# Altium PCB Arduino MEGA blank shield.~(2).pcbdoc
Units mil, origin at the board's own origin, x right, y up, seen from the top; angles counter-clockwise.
Board outline 4000 x 2100 mil, 2 copper layers (Top Layer, Bottom Layer); 8 components, 79 nets, 94 pads, 0 vias.
Unrouted connection lines stored in the file: 9.
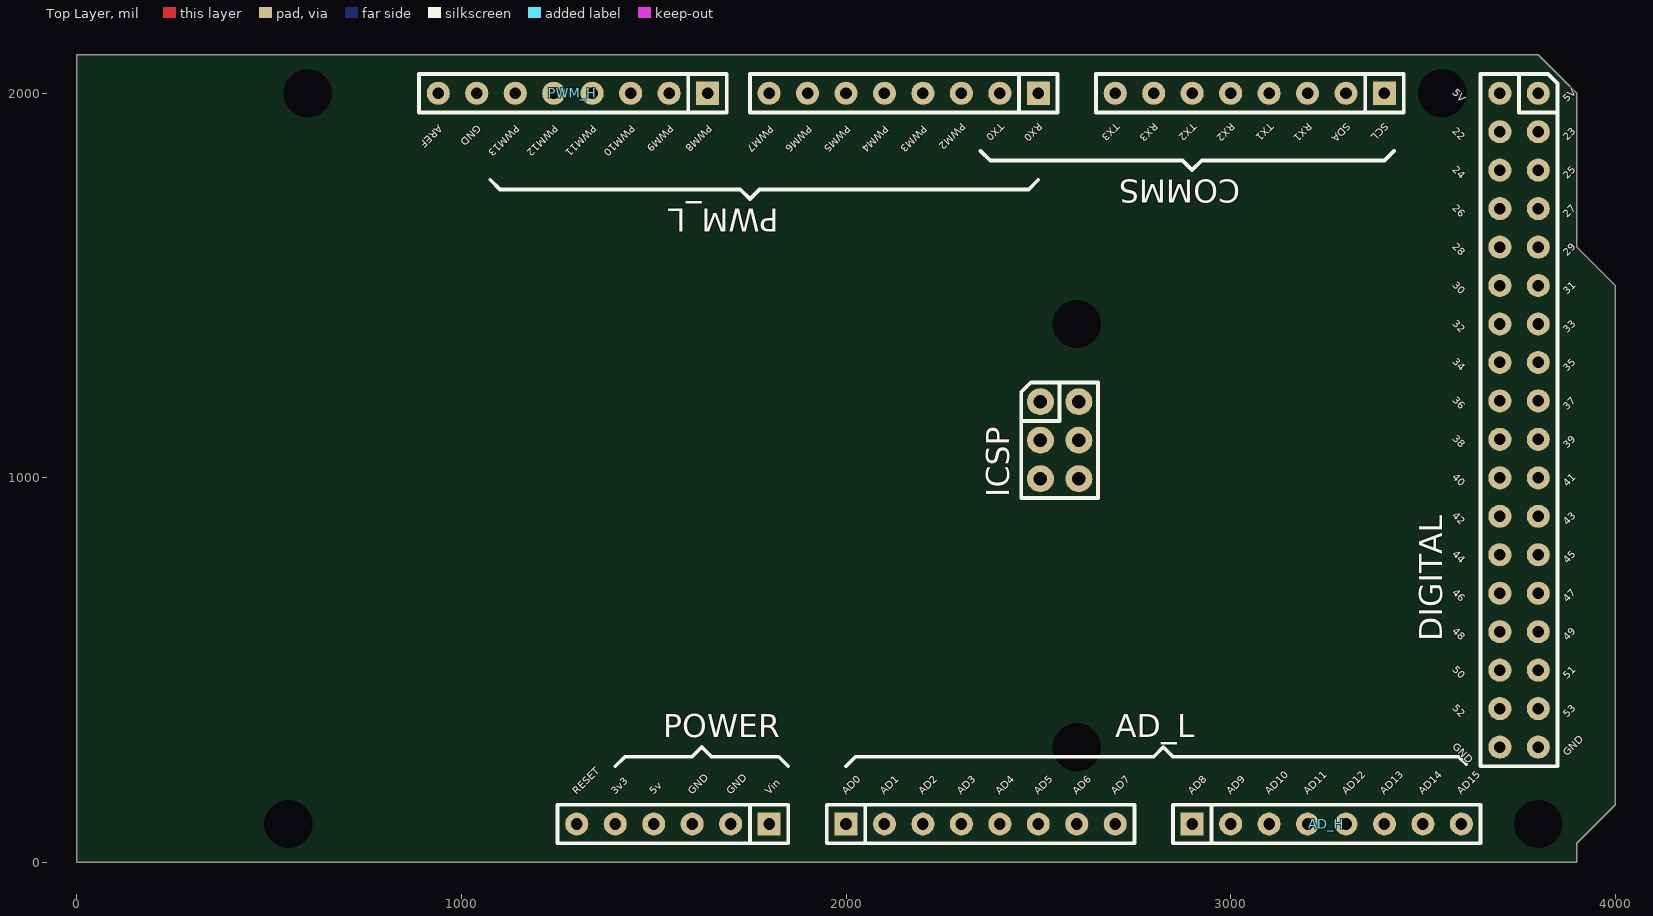
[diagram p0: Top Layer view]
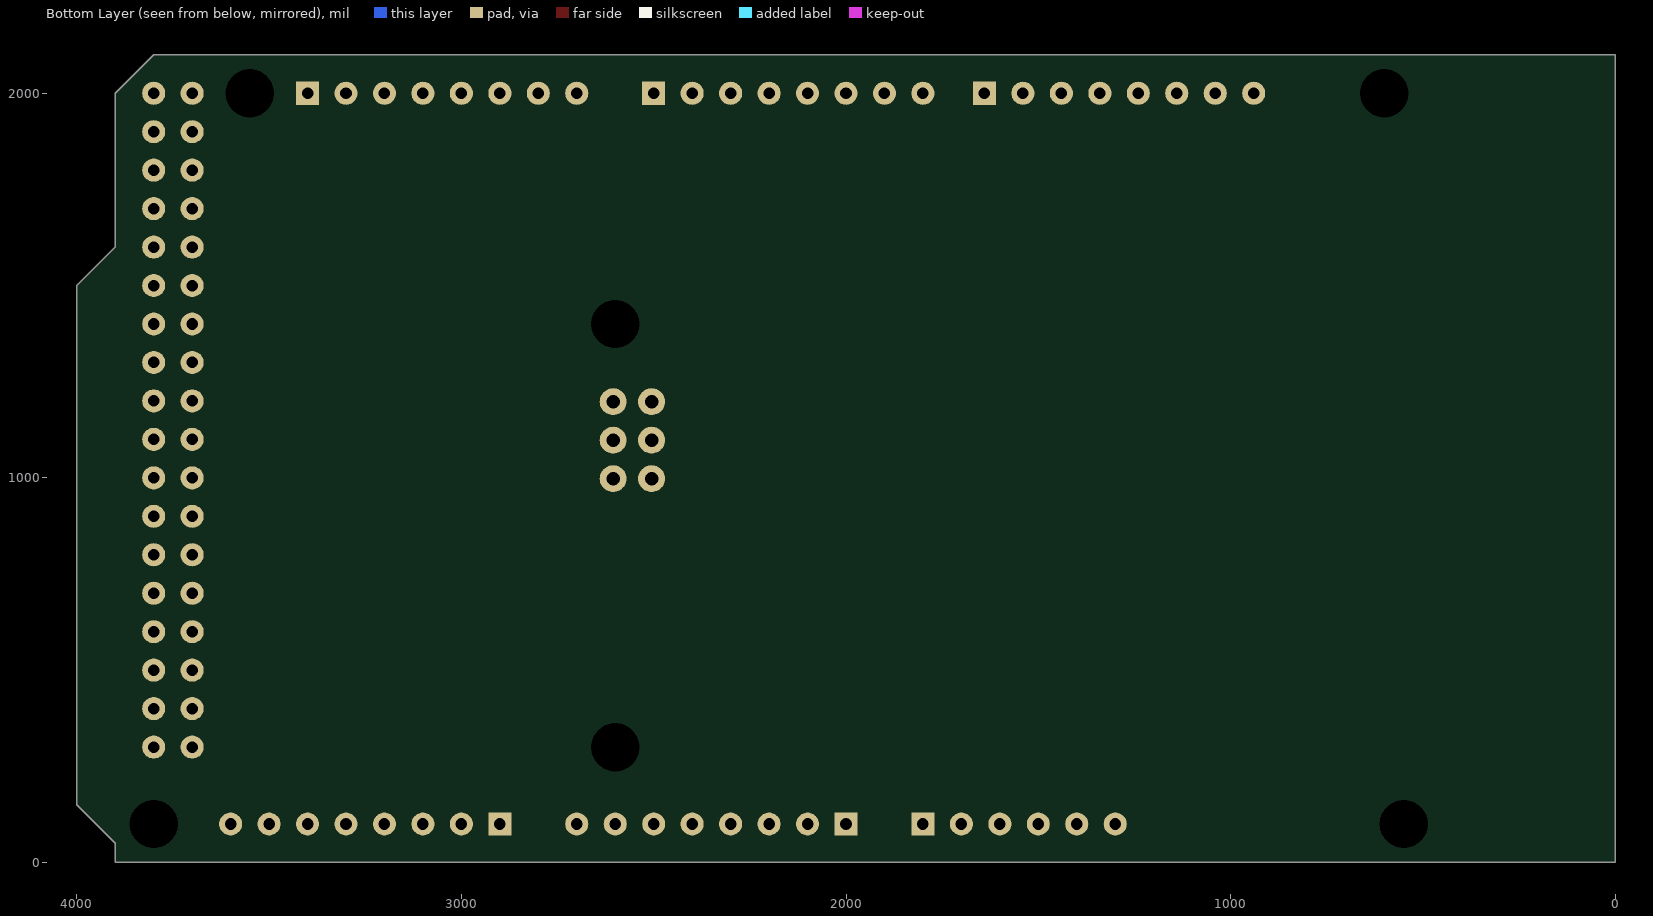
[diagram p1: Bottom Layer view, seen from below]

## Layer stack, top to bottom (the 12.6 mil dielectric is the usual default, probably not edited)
Top Solder: solder mask 0.4, Solder Resist, Dk 3.5
Top Layer: signal copper 1.4
Dielectric1: dielectric 12.6, FR-4, Dk 4.8
Bottom Layer: signal copper 1.4
Bottom Solder: solder mask 0.4, Solder Resist, Dk 3.5

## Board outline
0,0 0,2100 3800,2100 3900,2000 3900,1600 4000,1500 4000,150 3900,50 3900,0

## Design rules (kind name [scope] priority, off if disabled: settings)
Clearance [All] p1: gap=10 ignorepadtopadclearanceinfootprint=FALSE except(0: Arc-Hole Track-Hole SMDPad-Hole THPad-Hole Via-Hole Fill-Hole Poly-Hole Region-Hole Text-Hole)
PolygonConnect [All] p1: connectstyle=Relief reliefconductorwidth=10 reliefentries=4 polygonreliefangle="90 Angle" airgapwidth=10
RoomDefinition AdruinoMegaShield [InComponentClass('AdruinoMegaSheild')] p1: confinementstyle=ConfineOut formatcopy=TRUE lockcomponents=FALSE outline 4200,900 4750,900 4750,1080 4200,1080
RoutingVias [All] p1: holewidth=28 width=50 viastyle="Through Hole" minholewidth=28 minwidth=50 maxholewidth=28 maxwidth=50
SilkToSolderMaskClearance SilkscreenOverComponentPads [IsPad] p1: minsilkscreentomaskgap=10 clearancetoexposedcopper=TRUE
SolderMaskExpansion [All] p1: expansion=4 istentingtop=FALSE
Width [All] p1: maxlimit=10 minlimit=10 preferedwidth=10
29 further rules are at their usual default settings.

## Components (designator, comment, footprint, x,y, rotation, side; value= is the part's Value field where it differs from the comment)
AD_H "AD_H" "Header 8x1 8.5mm" 2900,100 r0 top locked
AD_L "AD_L" "Header 8x1 8.5mm" 2000,100 r0 top locked
COMMS "Communication" "Header 8x1 8.5mm" 3400,2000 r180 top
DIGITAL "IO_36" "HEADER 36X 8MM" 3800,2000 r270 top locked
ICSP "ICSP" ICSP 2505.51,1198.03 r0 top locked
POWER "POWER" "Header 6x1 8.5mm" 1800,100 r180 top locked
PWM_H "PWM_H" "Header 8x1 8.5mm" 1640,2000 r180 top locked
PWM_L "PWM_L" "Header 8x1 8.5mm" 2500,2000 r180 top locked

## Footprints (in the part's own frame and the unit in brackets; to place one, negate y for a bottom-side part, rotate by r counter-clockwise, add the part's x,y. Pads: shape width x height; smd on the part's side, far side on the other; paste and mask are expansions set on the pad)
"Header 6x1 8.5mm" [mil] "Stackable 6 pin header"
  rect 60x60 hole 30: 1(0,0)
  round 60 hole 30: 2(100,0) 3(200,0) 4(300,0) 5(400,0) 6(500,0)
  silkscreen extent -50,-50 550,50, body extent -50,-50 550,50, height 335
"Header 8x1 8.5mm" [mil] "Stackable 8 pin header"
  rect 60x60 hole 30: 1(0,0)
  round 60 hole 30: 2(100,0) 3(200,0) 4(300,0) 5(400,0) 6(500,0) 7(600,0) 8(700,0)
  silkscreen extent -50,-50 750,50, body extent -50,-50 750,50, height 335
"HEADER 36X 8MM" [mil] "Stackable 10 pin header"
  round 60 hole 30: 1(0,0) 2(0,-100) 3(100,0) 4(100,-100) 5(200,0) 6(200,-100) 7(300,0) 8(300,-100) 9(400,0) 10(400,-100) 11(500,0) 12(500,-100) 13(600,0) 14(600,-100) 15(700,0) 16(700,-100) 17(800,0) 18(800,-100) 19(900,-100) 20(900,0) 21(1000,0) 22(1000,-100) 23(1100,0) 24(1100,-100) 25(1200,0) 26(1200,-100) 27(1300,0) 28(1300,-100) 29(1400,0) 30(1400,-100) 31(1500,0) 32(1500,-100) 33(1600,0) 34(1600,-100) 35(1700,0) 36(1700,-100)
  silkscreen extent -50,-150 1750,50, body extent -50,-150 1750,50, height 335
ICSP [mil]
  round 70 hole 35.43: 1(0,0) 2(100,0) 3(0,-100) 4(100,-100) 5(0,-200) 6(100,-200)
  silkscreen extent -50,-250 150,50, body extent -50,-250 150,50, height 485

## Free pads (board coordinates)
  round 62.99 hole 125.98: 0(550,100) 0(600,2000) 0(2600,300) 0(2600,1400) 0(3550,2000) 0(3800,100)

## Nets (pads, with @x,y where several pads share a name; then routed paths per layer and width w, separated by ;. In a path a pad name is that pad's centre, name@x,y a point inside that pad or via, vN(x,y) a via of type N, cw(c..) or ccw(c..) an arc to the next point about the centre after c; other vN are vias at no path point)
3V3: POWER.5
5V: DIGITAL.1 DIGITAL.2 ICSP.2 POWER.4
AD0: AD_L.1
AD1: AD_L.2
AD2: AD_L.3
AD3: AD_L.4
AD4: AD_L.5
AD5: AD_L.6
AD6: AD_L.7
AD7: AD_L.8
AD8: AD_H.1
AD9: AD_H.2
AD10: AD_H.3
AD11: AD_H.4
AD12: AD_H.5
AD13: AD_H.6
AD14: AD_H.7
AD15: AD_H.8
AREF: PWM_H.8
GND: DIGITAL.35 DIGITAL.36 ICSP.6 POWER.2 POWER.3 PWM_H.7
IO22: DIGITAL.4
IO23: DIGITAL.3
IO24: DIGITAL.5
IO25: DIGITAL.6
IO26: DIGITAL.7
IO27: DIGITAL.8
IO28: DIGITAL.9
IO29: DIGITAL.10
IO30: DIGITAL.11
IO31: DIGITAL.12
IO32: DIGITAL.13
IO33: DIGITAL.14
IO34: DIGITAL.15
IO35: DIGITAL.16
IO36: DIGITAL.17
IO37: DIGITAL.18
IO38: DIGITAL.19
IO39: DIGITAL.20
IO40: DIGITAL.21
IO41: DIGITAL.22
IO42: DIGITAL.23
IO43: DIGITAL.24
IO44: DIGITAL.25
IO45: DIGITAL.26
IO46: DIGITAL.27
IO47: DIGITAL.28
IO48: DIGITAL.29
IO49: DIGITAL.30
IO50: DIGITAL.31
IO51: DIGITAL.32
IO52: DIGITAL.33
IO53: DIGITAL.34
MISO: ICSP.1
MOSI: ICSP.4
PWM2: PWM_L.3
PWM3: PWM_L.4
PWM4: PWM_L.5
PWM5: PWM_L.6
PWM6: PWM_L.7
PWM7: PWM_L.8
PWM8: PWM_H.1
PWM9: PWM_H.2
PWM10: PWM_H.3
PWM11: PWM_H.4
PWM12: PWM_H.5
PWM13: PWM_H.6
RESET: ICSP.5 POWER.6
RX0: PWM_L.1
RX1: COMMS.3
RX2: COMMS.5
RX3: COMMS.7
SCK: ICSP.3
SCL: COMMS.1
SDA: COMMS.2
TX0: PWM_L.2
TX1: COMMS.4
TX2: COMMS.6
TX3: COMMS.8
VIN: POWER.1

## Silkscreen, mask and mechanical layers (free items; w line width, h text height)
Top Overlay:
  lines w10: 1075,1775 1100,1750 1725,1750 1750,1725 1775,1750 2475,1750 2500,1775 ; 1400,250 1425,275 1600,275 1625,300 1650,275 1825,275 1850,250 ; 2000,250 2025,275 2800,275 2825,300 2850,275 3592.93,275 3612.7,255.23 ; 2350,1850 2375,1825 2875,1825 2900,1800 2925,1825 3400,1825 3425,1850
  text "5V" at 3575,2000 h20 r315
  text "5V" at 3875,1975 h20 r45
  text "PWM2" at 2300,1925 h20 r225
  text "TX0" at 2400,1925 h20 r225
  text "RX0" at 2500,1925 h20 r225
  text "TX3" at 2700,1925 h20 r225
  text "RX3" at 2800,1925 h20 r225
  text "TX2" at 2900,1925 h20 r225
  text "RX2" at 3000,1925 h20 r225
  text "TX1" at 3100,1925 h20 r225
  text "RX1" at 3200,1925 h20 r225
  text "SDA" at 3300,1925 h20 r225
  text "SCL" at 3400,1925 h20 r225
  text "AREF" at 940,1920 h20 r225
  text "GND" at 1040,1920 h20 r225
  text "PWM13" at 1140,1920 h20 r225
  text "PWM12" at 1240,1920 h20 r225
  text "PWM11" at 1340,1920 h20 r225
  text "PWM10" at 1440,1920 h20 r225
  text "PWM9" at 1540,1920 h20 r225
  text "PWM8" at 1640,1920 h20 r225
  text "PWM7" at 1800,1917.93 h20 r225
  text "PWM6" at 1900,1917.93 h20 r225
  text "PWM5" at 2000,1917.93 h20 r225
  text "PWM4" at 2100,1917.93 h20 r225
  text "PWM3" at 2200,1917.93 h20 r225
  text "22" at 3575,1900 h20 r315
  text "23" at 3875,1875 h20 r45
  text "24" at 3575,1800 h20 r315
  text "25" at 3875,1775 h20 r45
  text "26" at 3575,1700 h20 r315
  text "27" at 3875,1675 h20 r45
  text "28" at 3575,1600 h20 r315
  text "29" at 3875,1575 h20 r45
  text "30" at 3575,1500 h20 r315
  text "31" at 3875,1475 h20 r45
  text "32" at 3575,1400 h20 r315
  text "33" at 3875,1375 h20 r45
  text "34" at 3575,1300 h20 r315
  text "35" at 3875,1275 h20 r45
  text "36" at 3575,1200 h20 r315
  text "37" at 3875,1175 h20 r45
  text "38" at 3575,1100 h20 r315
  text "39" at 3875,1075 h20 r45
  text "40" at 3575,1000 h20 r315
  text "41" at 3875,975 h20 r45
  text "42" at 3575,900 h20 r315
  text "43" at 3875,875 h20 r45
  text "44" at 3575,800 h20 r315
  text "45" at 3875,775 h20 r45
  text "46" at 3575,700 h20 r315
  text "47" at 3875,675 h20 r45
  text "48" at 3575,600 h20 r315
  text "49" at 3875,575 h20 r45
  text "50" at 3575,500 h20 r315
  text "51" at 3875,475 h20 r45
  text "52" at 3575,400 h20 r315
  text "53" at 3875,375 h20 r45
  text "GND" at 3575,300 h20 r315
  text "GND" at 3875,275 h20 r45
  text "RESET" at 1300,175 h20 r45
  text "3v3" at 1400,175 h20 r45
  text "5v" at 1500,175 h20 r45
  text "GND" at 1600,175 h20 r45
  text "GND" at 1700,175 h20 r45
  text "Vin" at 1800,175 h20 r45
  text "AD0" at 2000,175 h20 r45
  text "AD1" at 2100,175 h20 r45
  text "AD2" at 2200,175 h20 r45
  text "AD3" at 2300,175 h20 r45
  text "AD4" at 2400,175 h20 r45
  text "AD5" at 2500,175 h20 r45
  text "AD6" at 2600,175 h20 r45
  text "AD7" at 2700,175 h20 r45
  text "AD8" at 2900,175 h20 r45
  text "AD9" at 3000,175 h20 r45
  text "AD10" at 3100,175 h20 r45
  text "AD11" at 3200,175 h20 r45
  text "AD12" at 3300,175 h20 r45
  text "AD13" at 3400,175 h20 r45
  text "AD14" at 3500,175 h20 r45
  text "AD15" at 3600,175 h20 r45
Mechanical 1:
  circle w5: c3800,100 r62.99
  circle w5: c3550,2000 r62.99
  circle w5: c2600,1400 r62.99
  circle w5: c550,100 r62.99
  circle w5: c2600,300 r62.99
  circle w5: c600,2000 r62.99
  lines w5: 0,0 0,2100 3800,2100 3900,2000 3900,1600 4000,1500 4000,150 3900,50 3900,0 0,0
